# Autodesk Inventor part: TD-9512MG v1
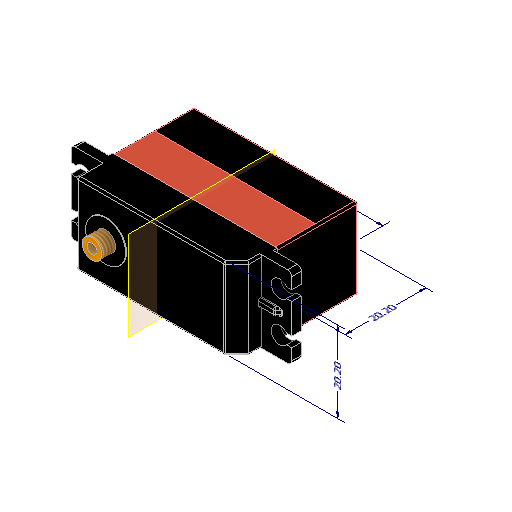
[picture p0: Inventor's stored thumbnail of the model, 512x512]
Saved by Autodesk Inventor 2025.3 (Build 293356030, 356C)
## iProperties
Created: 2025-01
Part Number: TD-9512MG v1
Material: Steel
Document SubType Name: Modeling
Designer: R5800u
Density: 7.85 g/cm^3
Appearance: Default
Sending System: Autodesk Translation Framework v13.20.0.188
Preprocessor: ST-DEVELOPER v20
Title: TD-9512MG v1.step
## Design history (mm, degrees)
node "Annotazioni"
  node "Quota lineare 1" dims "d61" = 20.2 (derived)
  node "Quota lineare 2" dims "d63" = 20.2 (derived)
  node "Quota lineare 3" dims "d72" = 41 (derived)
node "Body1"
feature "Body2"
feature "Body3"
sketch "Schizzo1"
  geometry: L1 (0, 0)-(0, -20.2) reference; L2 (0, -10.1)-(54, -10.1); L3 (54, 0)-(54, -20.2) reference; L4 (27, -10.1)-(27, 0); L5 (54, 0)-(0, 0) reference; L6 (3, -10.1)-(3, -5.1); 5 further points
  constraints: 6 end point, 4 midpoint, 3 symmetric about line, 1 coincident, 1 point on line, 1 vertical
  dimensions: "d10" = 5 distance of L6.start L6.end; "d11" = 24 distance between parallel lines of L4 L6
hole "Foro1" sketch "Schizzo1" at (3, -5.1), (3, -15.1), (51, -15.1), (51, -5.1) diameter "d12" = 5; stored, may be unused: countersink angle "d16" = 90 deg, drill point angle "d18" = 118 deg; dims "d13" = 6, "d14" = 4, "d15" = 2, "d17" = 8
sketch "Schizzo2"
  geometry: 1 further point
sketch "Schizzo3"
  geometry: L1 (0, 0)-(0, -20.2) reference; L2 (6, -16.35)-(0, -16.35); L3 (0, -16.35)-(0, -13.85); L4 (0, -13.85)-(6, -13.85); L5 (6, -13.85)-(6, -16.35); L6 (6, -16.35)-(0, -13.85); L7 (0, -16.35)-(6, -13.85); L8 (6, -3.85)-(0, -3.85); L9 (0, -3.85)-(0, -6.35); L10 (0, -6.35)-(6, -6.35); L11 (6, -6.35)-(6, -3.85); L12 (6, -3.85)-(0, -6.35); L13 (0, -3.85)-(6, -6.35); L14 (54, 0)-(0, 0) reference; L15 (27, 0)-(27, -20.2); L16 (0, -20.2)-(54, -20.2) reference; L17 (54, -16.35)-(54, -13.85); L18 (54, -13.85)-(48, -13.85); L19 (48, -16.35)-(54, -16.35); L20 (48, -16.35)-(54, -13.85); L21 (54, -16.35)-(48, -13.85); L22 (54, -6.35)-(48, -6.35); L23 (48, -6.35)-(48, -3.85); L24 (48, -3.85)-(54, -3.85); L25 (48, -3.85)-(54, -6.35); L26 (54, -3.85)-(48, -6.35); L27 (48, -13.85)-(48, -16.35); L28 (54, -3.85)-(54, -6.35); C1 r 2.5 at (3, -5.1) reference; C2 r 2.5 at (3, -15.1) reference; C3 r 2.5 at (51, -15.1); C4 r 2.5 at (51, -5.1); 12 further points
  constraints: 50 end point, 10 symmetric about line, 6 midpoint, 4 parallel, 2 centre point, 2 horizontal, 2 perpendicular, 1 point on line, 2 other
  dimensions: "d22" = 2.5 distance of L2.end L3.end; "d23" = 6 distance of L10.end L9.end; "d24" = 2.5 distance of L9.end L8.end
extrude "Estrusione1" cut sketch "Schizzo3" distance "d25" = 10; taper "d26" = 0 deg
sketch "Schizzo4"
  geometry: L1 (0, 20.2)-(0, 0) reference; L2 (0, 10.1)-(-5, 10.1); L3 (-5, 10.1)-(-5, 9.1); L4 (-5, 9.1)-(0, 9.1); L5 (0, 9.1)-(0, 10.1); L6 (-5, 10.1)-(0, 10.1); L7 (0, 10.1)-(0, 11.1); L8 (0, 11.1)-(-5, 11.1); L9 (-5, 11.1)-(-5, 10.1); L10 (47, 20.2)-(-7, 20.2) reference; L11 (20, 20.2)-(20, 0); L12 (-7, 0)-(47, 0) reference; L13 (40, 10.1)-(45, 10.1); L14 (45, 10.1)-(45, 9.1); L15 (45, 9.1)-(40, 9.1); L16 (40, 9.1)-(40, 10.1); L17 (45, 10.1)-(40, 10.1); L18 (40, 10.1)-(40, 11.1); L19 (40, 11.1)-(45, 11.1); L20 (45, 11.1)-(45, 10.1); 6 further points
  constraints: 34 end point, 7 symmetric about line, 4 parallel, 3 midpoint, 2 horizontal, 2 perpendicular, 1 point on line
  dimensions: "d28" = 5 distance of L4.end L3.end; "d29" = 1 distance of L3.end L2.end; "d30" = 1 distance of L7.end L6.end
extrude "Estrusione2" join sketch "Schizzo4" distance "d31" = 1; taper "d32" = 0 deg
chamfer "Smusso1" distance "d33" = 1; stored, may be unused: second distance "d34" = 2, angle "d35" = 45 deg
fillet "Raccordo2" dims "d36" = 0.5
sketch "Schizzo5"
  geometry: C1 r 2.45 at (7.5, -10.1) reference; C2 r 5 at (7.5, -10.1); 1 further point
  constraints: 1 centre point, 1 coincident
  dimensions: "d37" = 10 diameter of C2
extrude "Estrusione3" join sketch "Schizzo5" distance "d38" = 0.2; taper "d39" = 0 deg
sketch "Schizzo6"
  geometry: C1 r 2.45 at (0, 0) reference; 2 further points
  constraints: 1 coincident
hole "Foro2" sketch "Schizzo6" at (0, 0) diameter "d40" = 2.459; stored, may be unused: countersink angle "d44" = 81.933 deg, drill point angle "d46" = 118 deg; dims "d41" = 6, "d42" = 3.023, "d43" = 2, "d45" = 8.8
chamfer "Smusso2" distance "d47" = 0.2; stored, may be unused: second distance "d48" = 2, angle "d49" = 45 deg
sketch "Schizzo7"
  geometry: L1 (0, -2.5)-(-3.2, -2.5) reference; L2 (-3.2, -6.35)-(-3.2, -2.5) reference; L3 (0, -6.35)-(-3.2, -6.35) reference; L4 (0, -2.5)-(0, -6.35) reference; L5 (-3.2, 0)-(0, 0) reference; L6 (0, 7.5)-(0, 0) reference; L7 (0, 7.5)-(-3.2, 7.5) reference; L8 (-3.2, 0)-(-3.2, 7.5) reference; L9 (-3.2, 10)-(0, 10) reference; L10 (0, 13.85)-(0, 10) reference; L11 (0, 13.85)-(-3.2, 13.85) reference; L12 (-3.2, 10)-(-3.2, 13.85) reference; 1 further point
extrude "Estrusione4" join sketch "Schizzo7" distance "d51" = 0.5; taper "d52" = 0 deg
node "Piano di lavoro1"
mirror "Speculare1"
sketch "Schizzo8"
  geometry: L1 (0, 0)-(10, 0) reference; L2 (10, 0)-(10, 20.2) reference; L3 (0, 20.2)-(10, 20.2) reference; L4 (0, 0)-(0, 20.2) reference; L5 (0, 0)-(0, 20.2) reference; L6 (-8.2, 20.2)-(0, 20.2) reference; L7 (-8.2, 20.2)-(-8.2, 0) reference; L8 (-8.2, 0)-(0, 0) reference; 3 further points
extrude "Estrusione5" join sketch "Schizzo8" distance "d53" = 0.5; taper "d54" = 0 deg
mirror "Speculare2"
sketch "Schizzo9"
  geometry: L1 (-41, 20.2)-(0, 20.2) reference; L2 (-41, 20.2)-(-41, 0) reference; L3 (-41, 0)-(0, 0) reference; L4 (0, 20.2)-(0, 0) reference; 1 further point
extrude "Estrusione6" join sketch "Schizzo9" distance "d55" = 2; taper "d56" = 0 deg
fillet "Raccordo4" dims "d57" = 0.5
fillet "Raccordo5" dims "d58" = 1
sketch "Schizzo10"
  geometry: C1 r 3.536 at (0, 0); 1 further point
  constraints: 1 centre point
extrude "Estrusione7" cut sketch "Schizzo10" distance "d64" = 1.8; taper "d65" = 0 deg
sketch "Schizzo11"
  geometry: L1 (-3.5, 4.1)-(-3.5, 1.25) reference; L2 (-3.5, 1.25)-(-2.165, 1.25) reference; L3 (-2.165, -1.25)-(-3.5, -1.25) reference; L4 (-3.5, -1.25)-(-3.5, -8.75) reference; L5 (-3.5, -8.75)-(-2.165, -8.75) reference; L6 (-2.165, -11.25)-(-3.5, -11.25) reference; L7 (-3.5, -11.25)-(-3.5, -14.1) reference; L8 (-2.5, -15.1)-(4.5, -15.1) reference; L9 (4, -14.6)-(4, -6) reference; L10 (4, -6)-(-0.293, -6) reference; L11 (-1.207, -4.5)-(-1.207, -5.5) reference; L12 (-0.293, -4)-(4, -4) reference; L13 (4, -4)-(4, 4.6) reference; L14 (4.5, 5.1)-(-2.5, 5.1) reference; L15 (50.5, 5.1)-(43.5, 5.1) reference; L16 (44, 4.6)-(44, -4) reference; L17 (44, -4)-(48.293, -4) reference; L18 (49.207, -5.5)-(49.207, -4.5) reference; L19 (48.293, -6)-(44, -6) reference; L20 (44, -6)-(44, -14.6) reference; L21 (43.5, -15.1)-(50.5, -15.1) reference; L22 (51.5, -11.25)-(51.5, -14.1) reference; L23 (51.5, -11.25)-(50.165, -11.25) reference; L24 (50.165, -8.75)-(51.5, -8.75) reference; L25 (51.5, -1.25)-(51.5, -8.75) reference; L26 (51.5, -1.25)-(50.165, -1.25) reference; L27 (50.165, 1.25)-(51.5, 1.25) reference; L28 (51.5, 4.1)-(51.5, 1.25) reference; A1 r 1 centre (-2.5, 4.1) between (-2.5, 5.1) and (-3.5, 4.1) reference; A2 r 2.5 centre (0, 0) between (-2.165, -1.25) and (-2.165, 1.25) reference; A3 r 2.5 centre (0, -10) between (-2.165, -11.25) and (-2.165, -8.75) reference; A4 r 1 centre (-2.5, -14.1) between (-3.5, -14.1) and (-2.5, -15.1) reference; A5 r 0.5 centre (4.5, -14.6) between (4, -14.6) and (4.5, -15.1) reference; A6 r 0.5 centre (4.5, 4.6) between (4.5, 5.1) and (4, 4.6) reference; A7 r 1 centre (50.5, 4.1) between (51.5, 4.1) and (50.5, 5.1) reference; A8 r 0.5 centre (43.5, 4.6) between (44, 4.6) and (43.5, 5.1) reference; A9 r 0.5 centre (43.5, -14.6) between (43.5, -15.1) and (44, -14.6) reference; A10 r 1 centre (50.5, -14.1) between (50.5, -15.1) and (51.5, -14.1) reference; A11 r 2.5 centre (48, -10) between (50.165, -8.75) and (50.165, -11.25) reference; A12 r 2.5 centre (48, 0) between (50.165, 1.25) and (50.165, -1.25) reference; 9 further points; 4 other entities
  constraints: 8 other
  node "Linea chiusa proiettata7"
  node "Linea chiusa proiettata8"
sketch "Schizzo12"
  geometry: 1 further point
extrude "Estrusione8" join sketch "Schizzo11" distance "d66" = 0.2; taper "d67" = 0 deg
sketch "Schizzo13"
  geometry: L1 (-3.5, 1.25)-(-3.5, 4.1) reference; L2 (-3.5, 1.25)-(-2.165, 1.25) reference; L3 (-2.165, -1.25)-(-3.5, -1.25) reference; L4 (-3.5, -8.75)-(-3.5, -1.25) reference; L5 (-3.5, -8.75)-(-2.165, -8.75) reference; L6 (-2.165, -11.25)-(-3.5, -11.25) reference; L7 (-3.5, -14.1)-(-3.5, -11.25) reference; L8 (50.5, -15.1)-(-2.5, -15.1) reference; L9 (51.5, -14.1)-(51.5, -11.25) reference; L10 (51.5, -11.25)-(50.165, -11.25) reference; L11 (50.165, -8.75)-(51.5, -8.75) reference; L12 (51.5, -8.75)-(51.5, -1.25) reference; L13 (51.5, -1.25)-(50.165, -1.25) reference; L14 (50.165, 1.25)-(51.5, 1.25) reference; L15 (51.5, 1.25)-(51.5, 4.1) reference; L16 (-2.5, 5.1)-(50.5, 5.1) reference; L17 (44.523, -15.1)-(44.523, 5.1); L18 (3.493, -15.1)-(3.493, -15.039); L19 (3.493, -15.039)-(3.493, 5.1); A1 r 1 centre (-2.5, 4.1) between (-2.5, 5.1) and (-3.5, 4.1) reference; A2 r 2.5 centre (0, 0) between (-2.165, -1.25) and (-2.165, 1.25) reference; A3 r 2.5 centre (0, -10) between (-2.165, -11.25) and (-2.165, -8.75) reference; A4 r 1 centre (-2.5, -14.1) between (-3.5, -14.1) and (-2.5, -15.1) reference; A5 r 1 centre (50.5, -14.1) between (50.5, -15.1) and (51.5, -14.1) reference; A6 r 2.5 centre (48, -10) between (50.165, -8.75) and (50.165, -11.25) reference; A7 r 2.5 centre (48, 0) between (50.165, 1.25) and (50.165, -1.25) reference; A8 r 1 centre (50.5, 4.1) between (51.5, 4.1) and (50.5, 5.1) reference; 1 further point
  constraints: 6 end point, 5 point on line, 2 perpendicular
extrude "Estrusione9" cut sketch "Schizzo13" distance "d68" = 1; taper "d69" = 0 deg
feature "Filettatura1" dims "d73" = 3.4, "d74" = 0
sketch "Schizzo16"
  geometry: C1 r 2.5 at (48, -10); C2 r 2.5 at (48, 0); C3 r 2.5 at (0, -10); C4 r 2.5 at (0, 0); A1 r 2.5 centre (48, -10) between (50.165, -8.75) and (50.165, -11.25) reference; A2 r 2.5 centre (48, 0) between (50.165, 1.25) and (50.165, -1.25) reference; A3 r 2.5 centre (0, -10) between (-2.165, -11.25) and (-2.165, -8.75) reference; A4 r 2.5 centre (0, 0) between (-2.165, -1.25) and (-2.165, 1.25) reference; 9 further points
  constraints: 4 centre point, 4 coincident, 4 concentric
extrude "Estrusione10" join sketch "Schizzo16" stored distance "d75" = 1; taper "d76" = 0 deg
sketch "Schizzo17"
  geometry: L1 (48, -10)-(48.5, -10); L2 (48, 0)-(48.5, 0); C1 r 2.122 at (48.5, -10); C2 r 2.114 at (48.5, 0); A1 r 2.5 centre (48, -10) between (50.165, -11.25) and (50.165, -8.75) reference; A2 r 2.5 centre (48, 0) between (50.165, -1.25) and (50.165, 1.25) reference; A3 r 2.5 centre (0, -10) between (-2.165, -8.75) and (-2.165, -11.25) reference; A4 r 2.5 centre (0, 0) between (-2.165, 1.25) and (-2.165, -1.25) reference; 1 further point
  constraints: 4 end point, 2 centre point, 2 coincident, 2 horizontal
  dimensions: "d77" = 0.5 distance of L1.start L1.end; "d78" = 0.5 distance of L2.start L2.end
extrude "Estrusione11" cut sketch "Schizzo17" distance "d79" = 10; taper "d80" = 0 deg
mirror "Speculare3"
feature "ʘ耀ʚ耀ʜ耀ʞ耀ʠ耀ʢ耀ʤ耀ʦ耀" dims "d10" = 5, "d11" = 24, "d12" = 5, "d13" = 6, "d14" = 4, "d15" = 2, "d16" = 90 deg, "d17" = 8, "d18" = 118 deg, "d22" = 2.5, "d23" = 6, "d24" = 2.5, "d25" = 10, "d26" = 0, "d28" = 5, "d29" = 1, "d30" = 1, "d31" = 1, "d32" = 0, "d33" = 1, "d34" = 2, "d35" = 45 deg, "d36" = 0.5, "d37" = 10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
node "Solido1"
node "Solido2"
node "Solido3"
node "Linea chiusa proiettata1"
node "Linea chiusa proiettata2"
node "Linea chiusa proiettata3"
node "Linea chiusa proiettata4"
node "Linea chiusa proiettata5"
node "Linea chiusa proiettata6"
node "Linea chiusa proiettata9"
